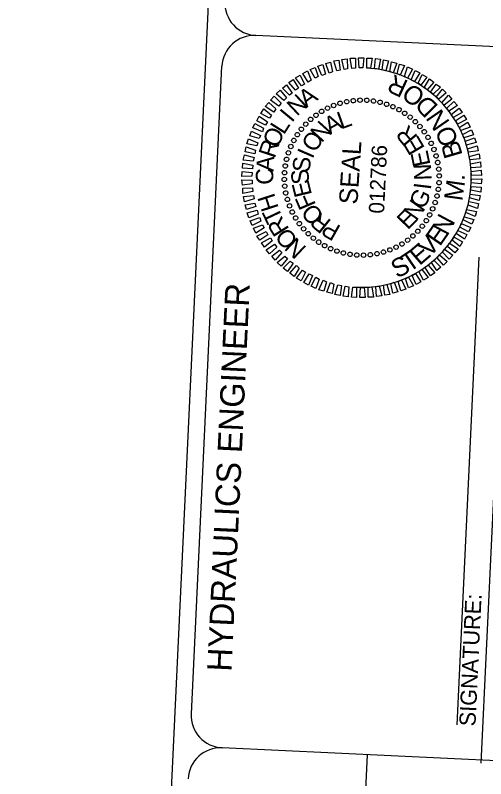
# Model space of a CAD drawing. Extents: x 2166609 to 2169084, y 841593 to 845234.
# Drawn here: x 2168488.8 to 2168793.4, y 844250.3 to 844744.4 of the extents above; entities that cross this region are included whole.
import ezdxf

# ---------------------------------------------------------------- set-up
doc = ezdxf.new("R2010")
doc.units = 0
for name, color, linetype in [('Scratch_Level_0', 7, 'Continuous'), ('Sheet Plan CELL', 7, 'Continuous'), ('Sheet Title CELL', 7, 'Continuous')]:
    doc.layers.add(name, color=color, linetype=linetype)

msp = doc.modelspace()

# ---------------------------------------------------------------- linework, layer by layer
at = {"layer": 'Scratch_Level_0'}
msp.add_arc((2168713.15, 844639.28), 71, 267.2959, 87.2959, dxfattribs=at)
at = {"layer": 'Sheet Plan CELL'}
for p, q in [((2168703.26, 844688.5), (2168703.26, 844688.5)), ((2168707.69, 844689.09), (2168707.69, 844689.09)), ((2168712.02, 844689.49), (2168712.02, 844689.49)), ((2168716.42, 844689.38), (2168716.42, 844689.38)), ((2168720.8, 844688.88), (2168720.8, 844688.88)), ((2168725.06, 844687.97), (2168725.06, 844687.97)), ((2168690.95, 844684.28), (2168690.95, 844684.28)), ((2168694.94, 844686.09), (2168694.94, 844686.09)), ((2168699.01, 844687.5), (2168699.01, 844687.5)), ((2168729.21, 844686.88), (2168729.21, 844686.88)), ((2168733.34, 844685.28), (2168733.34, 844685.28)), ((2168737.25, 844683.29), (2168737.25, 844683.29)), ((2168683.43, 844679.83), (2168683.43, 844679.83)), ((2168687.04, 844682.16), (2168687.04, 844682.16)), ((2168741.05, 844681.11), (2168741.05, 844681.11)), ((2168744.53, 844678.44), (2168744.53, 844678.44)), ((2168676.85, 844674.03), (2168676.85, 844674.03)), ((2168679.99, 844676.99), (2168679.99, 844676.99)), ((2168747.9, 844675.58), (2168747.9, 844675.58)), ((2168673.99, 844670.66), (2168673.99, 844670.66)), ((2168750.86, 844672.44), (2168750.86, 844672.44)), ((2168753.7, 844669), (2168753.7, 844669)), ((2168669.14, 844663.39), (2168669.14, 844663.39)), ((2168671.32, 844667.19), (2168671.32, 844667.19)), ((2168756.03, 844665.39), (2168756.03, 844665.39)), ((2168667.15, 844659.47), (2168667.15, 844659.47)), ((2168758.15, 844661.48), (2168758.15, 844661.48)), ((2168665.55, 844655.35), (2168665.55, 844655.35)), ((2168759.96, 844657.49), (2168759.96, 844657.49)), ((2168761.37, 844653.42), (2168761.37, 844653.42)), ((2168664.46, 844651.19), (2168664.46, 844651.19)), ((2168762.37, 844649.17), (2168762.37, 844649.17)), ((2168663.55, 844646.93), (2168663.55, 844646.93)), ((2168762.96, 844644.74), (2168762.96, 844644.74)), ((2168663.05, 844642.55), (2168663.05, 844642.55)), ((2168713.15, 844639.28), (2168713.15, 844639.28)), ((2168763.36, 844640.41), (2168763.36, 844640.41)), ((2168662.94, 844638.15), (2168662.94, 844638.15)), ((2168663.34, 844633.83), (2168663.34, 844633.83)), ((2168763.25, 844636.01), (2168763.25, 844636.01)), ((2168663.93, 844629.39), (2168663.93, 844629.39)), ((2168762.74, 844631.63), (2168762.74, 844631.63)), ((2168664.93, 844625.14), (2168664.93, 844625.14)), ((2168761.84, 844627.37), (2168761.84, 844627.37)), ((2168666.34, 844621.07), (2168666.34, 844621.07)), ((2168759.15, 844619.09), (2168759.15, 844619.09)), ((2168760.74, 844623.22), (2168760.74, 844623.22)), ((2168668.15, 844617.08), (2168668.15, 844617.08)), ((2168757.16, 844615.18), (2168757.16, 844615.18)), ((2168670.27, 844613.18), (2168670.27, 844613.18)), ((2168672.6, 844609.56), (2168672.6, 844609.56)), ((2168754.98, 844611.38), (2168754.98, 844611.38)), ((2168675.44, 844606.12), (2168675.44, 844606.12)), ((2168749.45, 844604.53), (2168749.45, 844604.53)), ((2168752.31, 844607.9), (2168752.31, 844607.9)), ((2168678.4, 844602.98), (2168678.4, 844602.98)), ((2168681.77, 844600.12), (2168681.77, 844600.12)), ((2168746.31, 844601.58), (2168746.31, 844601.58)), ((2168685.24, 844597.45), (2168685.24, 844597.45)), ((2168689.05, 844595.27), (2168689.05, 844595.27)), ((2168735.35, 844594.28), (2168735.35, 844594.28)), ((2168739.26, 844596.4), (2168739.26, 844596.4)), ((2168742.87, 844598.73), (2168742.87, 844598.73)), ((2168692.96, 844593.28), (2168692.96, 844593.28)), ((2168697.09, 844591.69), (2168697.09, 844591.69)), ((2168701.24, 844590.59), (2168701.24, 844590.59)), ((2168705.5, 844589.69), (2168705.5, 844589.69)), ((2168709.88, 844589.18), (2168709.88, 844589.18)), ((2168714.28, 844589.07), (2168714.28, 844589.07)), ((2168718.61, 844589.47), (2168718.61, 844589.47)), ((2168723.04, 844590.06), (2168723.04, 844590.06)), ((2168727.29, 844591.06), (2168727.29, 844591.06)), ((2168731.36, 844592.47), (2168731.36, 844592.47)), ((2168630.24, 844566.91), (2168630.24, 844566.91))]:
    msp.add_line(p, q, dxfattribs=at)
for points in [[(2168687.34, 844705.37), (2168684.62, 844711.41), (2168687.88, 844712.56), (2168689.58, 844706.27)], [(2168692.12, 844706.95), (2168689.81, 844713.17), (2168692.96, 844714.12), (2168694.26, 844707.85)], [(2168696.99, 844708.32), (2168694.99, 844714.82), (2168698.32, 844715.27), (2168699.12, 844708.92)], [(2168701.84, 844709.29), (2168700.24, 844715.68), (2168703.66, 844716.11), (2168703.97, 844709.79)], [(2168706.68, 844709.97), (2168705.58, 844716.52), (2168709, 844716.66), (2168709.09, 844710.25)], [(2168711.5, 844710.34), (2168711.01, 844716.87), (2168714.41, 844716.91), (2168713.91, 844710.43)], [(2168716.5, 844710.2), (2168716.51, 844716.71), (2168719.9, 844716.55), (2168718.9, 844710.09)], [(2168721.49, 844709.87), (2168721.99, 844716.35), (2168725.28, 844715.99), (2168723.88, 844709.55)], [(2168726.26, 844709.14), (2168727.16, 844715.51), (2168730.54, 844714.95), (2168728.63, 844708.53)], [(2168731.32, 844708.1), (2168732.41, 844714.26), (2168735.77, 844713.4), (2168733.38, 844707.2)], [(2168736.05, 844706.58), (2168737.64, 844712.71), (2168740.9, 844711.85), (2168738.11, 844705.68)], [(2168678.43, 844701.19), (2168674.89, 844706.66), (2168677.97, 844708.42), (2168680.49, 844702.49)], [(2168682.95, 844703.58), (2168679.72, 844709.34), (2168682.87, 844710.49), (2168684.9, 844704.69)], [(2168740.77, 844704.85), (2168742.86, 844710.96), (2168745.9, 844709.51), (2168742.82, 844703.65)], [(2168745.07, 844702.65), (2168747.66, 844708.73), (2168750.69, 844707.09), (2168747.22, 844701.54)], [(2168670.18, 844695.97), (2168665.9, 844700.78), (2168668.69, 844702.75), (2168672.24, 844697.28)], [(2168674.21, 844698.79), (2168670.25, 844703.88), (2168673.24, 844705.64), (2168676.17, 844699.89)], [(2168749.57, 844700.43), (2168752.34, 844706.01), (2168755.37, 844704.36), (2168751.42, 844699.14)], [(2168753.76, 844697.83), (2168757.02, 844703.28), (2168759.72, 844701.15), (2168755.48, 844696.15)], [(2168666.41, 844692.65), (2168661.92, 844697.16), (2168664.43, 844699.45), (2168668.08, 844694.07)], [(2168757.61, 844694.65), (2168761.26, 844699.88), (2168764.07, 844697.84), (2168759.45, 844693.26)], [(2168662.75, 844689.22), (2168657.75, 844693.56), (2168660.26, 844695.84), (2168664.34, 844691.04)], [(2168761.26, 844691.47), (2168765.41, 844696.48), (2168767.9, 844694.16), (2168763, 844689.99)], [(2168764.9, 844687.79), (2168769.23, 844692.7), (2168771.41, 844690.09), (2168766.42, 844686.12)], [(2168656.28, 844681.61), (2168650.65, 844685.38), (2168652.87, 844687.88), (2168657.59, 844683.75)], [(2168659.47, 844685.57), (2168654.15, 844689.52), (2168656.47, 844692.01), (2168660.96, 844687.4)], [(2168768.24, 844684.33), (2168772.84, 844688.52), (2168775.12, 844686.01), (2168769.54, 844682.37)], [(2168653.4, 844677.84), (2168647.84, 844680.81), (2168649.68, 844683.73), (2168654.69, 844679.68)], [(2168771.14, 844680.19), (2168776.14, 844684.26), (2168778.11, 844681.46), (2168772.35, 844678.23)], [(2168650.89, 844673.36), (2168645.11, 844676.13), (2168646.66, 844679.16), (2168652.09, 844675.5)], [(2168773.96, 844676.25), (2168779.23, 844679.71), (2168781.01, 844677.02), (2168775.06, 844674)], [(2168648.78, 844668.95), (2168642.59, 844671.55), (2168643.92, 844674.29), (2168649.58, 844671.22)], [(2168776.25, 844671.74), (2168781.82, 844675.18), (2168783.27, 844672.01), (2168777.36, 844669.79)], [(2168646.77, 844664.54), (2168640.64, 844666.33), (2168641.79, 844669.38), (2168647.57, 844666.61)], [(2168778.45, 844667.33), (2168784.19, 844670.26), (2168785.44, 844667.1), (2168779.24, 844665.09)], [(2168645.24, 844659.81), (2168638.8, 844661.11), (2168639.76, 844664.47), (2168645.84, 844661.88)], [(2168780.34, 844662.84), (2168786.25, 844665.16), (2168787.31, 844662.11), (2168780.82, 844660.31)], [(2168643.9, 844654.77), (2168637.55, 844655.97), (2168638.21, 844659.24), (2168644.32, 844657.15)], [(2168781.7, 844657.87), (2168787.8, 844659.88), (2168788.56, 844656.74), (2168782.3, 844655.74)], [(2168642.88, 844650.01), (2168636.4, 844650.72), (2168637.16, 844653.98), (2168643.39, 844652.39)], [(2168782.77, 844653.01), (2168789.17, 844654.81), (2168789.71, 844651.38), (2168783.17, 844650.89)], [(2168642.34, 844645.03), (2168635.85, 844645.34), (2168636.1, 844648.63), (2168642.55, 844647.42)], [(2168783.65, 844648.17), (2168790.11, 844649.46), (2168790.26, 844646.15), (2168783.83, 844645.75)], [(2168642.01, 844640.24), (2168635.5, 844640.05), (2168635.75, 844643.34), (2168642.23, 844642.63)], [(2168784.02, 844643.34), (2168790.46, 844644.14), (2168790.7, 844640.72), (2168784.21, 844640.93)], [(2168784.28, 844638.32), (2168790.8, 844638.52), (2168790.54, 844635.23), (2168784.07, 844635.93)], [(2168642.28, 844635.22), (2168635.83, 844634.42), (2168635.59, 844637.84), (2168642.09, 844637.63)], [(2168783.96, 844633.53), (2168790.45, 844633.23), (2168790.19, 844629.94), (2168783.74, 844631.14)], [(2168642.65, 844630.4), (2168636.18, 844629.1), (2168636.04, 844632.41), (2168642.46, 844632.81)], [(2168783.42, 844628.55), (2168789.9, 844627.85), (2168789.14, 844624.58), (2168782.91, 844626.18)], [(2168643.52, 844625.55), (2168637.13, 844623.75), (2168636.59, 844627.18), (2168643.12, 844627.67)], [(2168782.4, 844623.8), (2168788.75, 844622.6), (2168788.09, 844619.32), (2168781.98, 844621.41)], [(2168644.6, 844620.7), (2168638.49, 844618.68), (2168637.74, 844621.82), (2168644, 844622.83)], [(2168781.06, 844618.76), (2168787.5, 844617.45), (2168786.54, 844614.09), (2168780.46, 844616.68)], [(2168645.96, 844615.73), (2168640.05, 844613.4), (2168638.99, 844616.46), (2168645.48, 844618.25)], [(2168779.53, 844614.02), (2168785.65, 844612.23), (2168784.51, 844609.18), (2168778.73, 844611.96)], [(2168647.85, 844611.23), (2168642.11, 844608.3), (2168640.86, 844611.46), (2168647.06, 844613.47)], [(2168650.05, 844606.82), (2168644.48, 844603.38), (2168643.03, 844606.55), (2168648.94, 844608.78)], [(2168777.52, 844609.61), (2168783.71, 844607.02), (2168782.37, 844604.28), (2168776.71, 844607.35)], [(2168652.34, 844602.31), (2168647.07, 844598.85), (2168645.29, 844601.54), (2168651.24, 844604.56)], [(2168775.41, 844605.21), (2168781.19, 844602.43), (2168779.64, 844599.4), (2168774.21, 844603.06)], [(2168655.15, 844598.37), (2168650.16, 844594.3), (2168648.19, 844597.1), (2168653.95, 844600.33)], [(2168772.9, 844600.72), (2168778.46, 844597.75), (2168776.62, 844594.84), (2168771.61, 844598.88)], [(2168658.06, 844594.23), (2168653.46, 844590.04), (2168651.18, 844592.55), (2168656.75, 844596.19)], [(2168770.02, 844596.95), (2168775.64, 844593.18), (2168773.42, 844590.68), (2168768.71, 844594.81)], [(2168661.4, 844590.77), (2168657.07, 844585.87), (2168654.89, 844588.47), (2168659.88, 844592.44)], [(2168763.55, 844589.35), (2168768.55, 844585.01), (2168766.04, 844582.72), (2168761.96, 844587.52)], [(2168766.83, 844593), (2168772.14, 844589.04), (2168769.82, 844586.55), (2168765.34, 844591.17)], [(2168665.03, 844587.09), (2168660.89, 844582.08), (2168658.4, 844584.4), (2168663.3, 844588.58)], [(2168668.69, 844583.92), (2168665.04, 844578.68), (2168662.23, 844580.72), (2168666.85, 844585.31)], [(2168759.88, 844585.92), (2168764.38, 844581.4), (2168761.86, 844579.12), (2168758.21, 844584.49)], [(2168672.54, 844580.73), (2168669.28, 844575.28), (2168666.58, 844577.41), (2168670.82, 844582.42)], [(2168676.72, 844578.13), (2168673.96, 844572.56), (2168670.93, 844574.2), (2168674.88, 844579.42)], [(2168752.09, 844579.78), (2168756.05, 844574.69), (2168753.06, 844572.92), (2168750.13, 844578.67)], [(2168756.12, 844582.59), (2168760.4, 844577.78), (2168757.6, 844575.81), (2168754.06, 844581.29)], [(2168681.22, 844575.92), (2168678.63, 844569.83), (2168675.61, 844571.48), (2168679.07, 844577.02)], [(2168685.52, 844573.71), (2168683.43, 844567.6), (2168680.4, 844569.05), (2168683.48, 844574.91)], [(2168743.35, 844574.99), (2168746.58, 844569.23), (2168743.42, 844568.07), (2168741.39, 844573.88)], [(2168747.87, 844577.38), (2168751.41, 844571.9), (2168748.33, 844570.15), (2168745.8, 844576.07)], [(2168690.25, 844571.99), (2168688.66, 844565.86), (2168685.39, 844566.71), (2168688.19, 844572.89)], [(2168694.98, 844570.46), (2168693.89, 844564.31), (2168690.53, 844565.17), (2168692.92, 844571.36)], [(2168700.04, 844569.42), (2168699.14, 844563.06), (2168695.76, 844563.62), (2168697.66, 844570.04)], [(2168724.46, 844569.27), (2168726.06, 844562.89), (2168722.63, 844562.45), (2168722.33, 844568.77)], [(2168729.31, 844570.24), (2168731.31, 844563.74), (2168727.98, 844563.3), (2168727.18, 844569.64)], [(2168734.18, 844571.61), (2168736.49, 844565.4), (2168733.34, 844564.45), (2168732.04, 844570.71)], [(2168738.96, 844573.19), (2168741.68, 844567.16), (2168738.42, 844566.01), (2168736.71, 844572.3)], [(2168704.81, 844568.7), (2168704.3, 844562.21), (2168701.02, 844562.57), (2168702.42, 844569.01)], [(2168709.8, 844568.36), (2168709.79, 844561.85), (2168706.4, 844562.01), (2168707.4, 844568.47)], [(2168714.8, 844568.22), (2168715.29, 844561.69), (2168711.89, 844561.66), (2168712.39, 844568.14)], [(2168719.62, 844568.6), (2168720.71, 844562.04), (2168717.3, 844561.9), (2168717.21, 844568.31)]]:
    msp.add_lwpolyline(points, close=True, dxfattribs=at)
for centre, major_axis in [((2168699.07, 844687.43), (-0.4, 1.38)), ((2168703.32, 844688.47), (-0.28, 1.41)), ((2168707.65, 844689.14), (-0.16, 1.43)), ((2168712.01, 844689.43), (-0.03, 1.44)), ((2168716.39, 844689.34), (0.09, 1.44)), ((2168720.74, 844688.86), (0.22, 1.42)), ((2168725.03, 844688.01), (0.34, 1.4)), ((2168729.23, 844686.79), (0.46, 1.36)), ((2168687.09, 844682.14), (-0.75, 1.23)), ((2168690.93, 844684.25), (-0.64, 1.29)), ((2168694.93, 844686.02), (-0.52, 1.34)), ((2168733.31, 844685.21), (0.58, 1.32)), ((2168737.24, 844683.28), (0.69, 1.26)), ((2168680.05, 844676.97), (-0.95, 1.08)), ((2168683.46, 844679.71), (-0.85, 1.16)), ((2168740.98, 844681.01), (0.8, 1.2)), ((2168744.51, 844678.43), (0.9, 1.12)), ((2168676.89, 844673.94), (-1.04, 0.99)), ((2168747.81, 844675.54), (0.99, 1.04)), ((2168750.83, 844672.38), (1.08, 0.95)), ((2168671.42, 844667.12), (-1.2, 0.8)), ((2168674, 844670.65), (-1.12, 0.9)), ((2168753.58, 844668.97), (1.16, 0.85)), ((2168669.15, 844663.37), (-1.26, 0.69)), ((2168756.01, 844665.34), (1.23, 0.75)), ((2168758.12, 844661.5), (1.29, 0.64)), ((2168667.22, 844659.45), (-1.32, 0.58)), ((2168759.88, 844657.5), (1.34, 0.52)), ((2168665.64, 844655.37), (-1.36, 0.46)), ((2168761.29, 844653.36), (1.38, 0.4)), ((2168663.57, 844646.87), (-1.42, 0.22)), ((2168664.42, 844651.17), (-1.4, 0.34)), ((2168762.34, 844649.11), (1.41, 0.28)), ((2168663.09, 844642.52), (-1.44, 0.09)), ((2168763.01, 844644.78), (1.43, 0.16)), ((2168663, 844638.15), (-1.44, -0.03)), ((2168763.3, 844640.42), (1.44, 0.03)), ((2168663.29, 844633.78), (-1.43, -0.16)), ((2168763.2, 844636.04), (1.44, -0.09)), ((2168663.96, 844629.46), (-1.41, -0.28)), ((2168761.88, 844627.4), (1.4, -0.34)), ((2168762.73, 844631.69), (1.42, -0.22)), ((2168665, 844625.21), (-1.38, -0.4)), ((2168760.66, 844623.2), (1.36, -0.46)), ((2168666.41, 844621.06), (-1.34, -0.52)), ((2168668.18, 844617.06), (-1.29, -0.64)), ((2168759.08, 844619.12), (1.32, -0.58)), ((2168670.29, 844613.23), (-1.23, -0.75)), ((2168757.14, 844615.19), (1.26, -0.69)), ((2168672.72, 844609.59), (-1.16, -0.85)), ((2168752.29, 844607.92), (1.12, -0.9)), ((2168754.88, 844611.45), (1.2, -0.8)), ((2168675.46, 844606.18), (-1.08, -0.95)), ((2168678.49, 844603.02), (-0.99, -1.04)), ((2168749.41, 844604.62), (1.04, -0.99)), ((2168681.78, 844600.14), (-0.9, -1.12)), ((2168685.32, 844597.55), (-0.8, -1.2)), ((2168742.84, 844598.85), (0.85, -1.16)), ((2168746.25, 844601.6), (0.95, -1.08)), ((2168689.06, 844595.29), (-0.69, -1.26)), ((2168692.98, 844593.35), (-0.58, -1.32)), ((2168731.37, 844592.55), (0.52, -1.34)), ((2168735.37, 844594.31), (0.64, -1.29)), ((2168739.21, 844596.42), (0.75, -1.23)), ((2168697.06, 844591.77), (-0.46, -1.36)), ((2168701.27, 844590.55), (-0.34, -1.4)), ((2168705.56, 844589.7), (-0.22, -1.42)), ((2168709.91, 844589.23), (-0.09, -1.44)), ((2168714.28, 844589.13), (0.03, -1.44)), ((2168718.65, 844589.42), (0.16, -1.43)), ((2168722.97, 844590.09), (0.28, -1.41)), ((2168727.22, 844591.14), (0.4, -1.38))]:
    msp.add_ellipse(centre, major_axis=major_axis, ratio=0.999708, dxfattribs=at)
at = {"layer": 'Sheet Title CELL'}
for p, q in [((2168488.78, 842100.73), (2168629.46, 845079.4)), ((2168980.18, 844715.47), (2168644.55, 844731.32)), ((2168790.45, 844260.51), (2168812.32, 844723.4)), ((2168602.79, 844292.29), (2168622.59, 844711.34)), ((2168774.83, 844285.2), (2168789.12, 844587.79)), ((2168958.43, 844254.47), (2168622.81, 844270.32)), ((2168716.68, 844265.88), (2168686.43, 843626.1))]:
    msp.add_line(p, q, dxfattribs=at)
for centre, start, end in [((2168645.54, 844752.3), 177.2959, 267.2959), ((2168643.56, 844710.35), 87.2959, 177.2959), ((2168623.68, 844291.31), 177.2959, 267.2959), ((2168621.7, 844249.36), 87.2959, 177.2959)]:
    msp.add_arc(centre, 21, start, end, dxfattribs=at)

# ---------------------------------------------------------------- texts
at = {"layer": 'Sheet Plan CELL'}
for s, height, rotation, p in [('R', 12, 155.2134, (2168743.99, 844701.62)), ('O', 12, 144.2334, (2168755.14, 844693.78)), ('N', 11.28, 43.1148, (2168671.16, 844678.61)), ('A', 11.28, 35.9131, (2168677.33, 844684.22)), ('D', 12, 134.8534, (2168763.33, 844685.5)), ('I', 11.28, 50.3161, (2168667.86, 844674.46)), ('N', 12, 124.6661, (2168770.57, 844675.14)), ('A', 11.28, 29.0562, (2168692.63, 844666.88)), ('L', 11.28, 19.6968, (2168699.7, 844670.45)), ('L', 11.28, 57.5168, (2168662.68, 844666.59)), ('N', 11.28, 47.7725, (2168687.17, 844661.43)), ('R', 11.28, 129.7773, (2168749.94, 844665.78)), ('O', 11.28, 64.7171, (2168658.57, 844657.98)), ('O', 11.28, 57.1294, (2168682.85, 844654.93)), ('O', 12, 113.6861, (2168776.19, 844662.72)), ('R', 11.28, 71.917, (2168656.76, 844651.36)), ('E', 11.28, 120.42, (2168754.3, 844658.46)), ('SEAL', 11.996, 86.2959, (2168710.32, 844621.7)), ('012786', 9.949, 87.2959, (2168727.57, 844615.89)), ('B', 12, 106.3759, (2168778.57, 844653.96)), ('I', 11.28, 66.4855, (2168681.27, 844651)), ('E', 11.28, 101.7077, (2168757.7, 844647.69)), ('A', 11.28, 86.3162, (2168655.96, 844642.98)), ('S', 11.28, 85.1963, (2168679.46, 844642.47)), ('C', 11.28, 93.5158, (2168656.19, 844635.06)), ('S', 11.28, 94.5515, (2168679.22, 844635.28)), ('N', 11.28, 92.3523, (2168758.43, 844637.74)), ('.', 12, 92.8565, (2168779.97, 844637.25)), ('E', 11.28, 103.907, (2168680.99, 844628.29)), ('I', 11.28, 82.9971, (2168757.81, 844631.07)), ('M', 12, 81.9058, (2168778.21, 844623.77)), ('H', 11.28, 107.9154, (2168659.47, 844619.69)), ('G', 11.28, 64.2862, (2168753.4, 844618.16)), ('F', 11.28, 113.263, (2168683.69, 844621.75)), ('N', 11.28, 54.9299, (2168748.54, 844610.78)), ('O', 11.28, 131.9772, (2168689.27, 844614.88)), ('E', 11.28, 45.5728, (2168742.87, 844605.04)), ('T', 11.28, 115.1157, (2168662.45, 844613.04)), ('R', 11.28, 122.3164, (2168666.53, 844606.04)), ('R', 11.28, 141.3356, (2168694, 844611.15)), ('N', 12, 62.0303, (2168768.65, 844601.12)), ('P', 11.28, 150.6948, (2168700.24, 844607.66)), ('E', 12, 55.2779, (2168763.7, 844594.35)), ('O', 11.28, 129.5177, (2168672.4, 844598.86)), ('N', 11.28, 136.7194, (2168677.97, 844593.99)), ('V', 12, 47.4393, (2168757, 844587.29)), ('E', 12, 40.6869, (2168750.51, 844581.98)), ('T', 12, 34.2281, (2168743.75, 844577.66)), ('S', 12, 27.2702, (2168735.97, 844573.88))]:
    msp.add_text(s, height=height, rotation=rotation, dxfattribs=at).set_placement(p)
at = {"layer": 'Sheet Title CELL'}
for s, height, p in [(' HYDRAULICS ENGINEER', 15.75, (2168628.53, 844313.57)), ('SIGNATURE:', 10.499, (2168786.74, 844284.06))]:
    msp.add_text(s, height=height, rotation=87.2959, dxfattribs=at).set_placement(p)

doc.saveas('drawing.dxf')
